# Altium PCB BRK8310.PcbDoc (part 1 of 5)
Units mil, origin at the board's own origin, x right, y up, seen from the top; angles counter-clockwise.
Board outline 6600.39 x 4492.13 mil, 4 copper layers (L1-Top, L2-GND, L3-GND, L4-BOT), stack 60.25 mil thick; 119 components, 266 nets, 1026 pads, 596 vias.
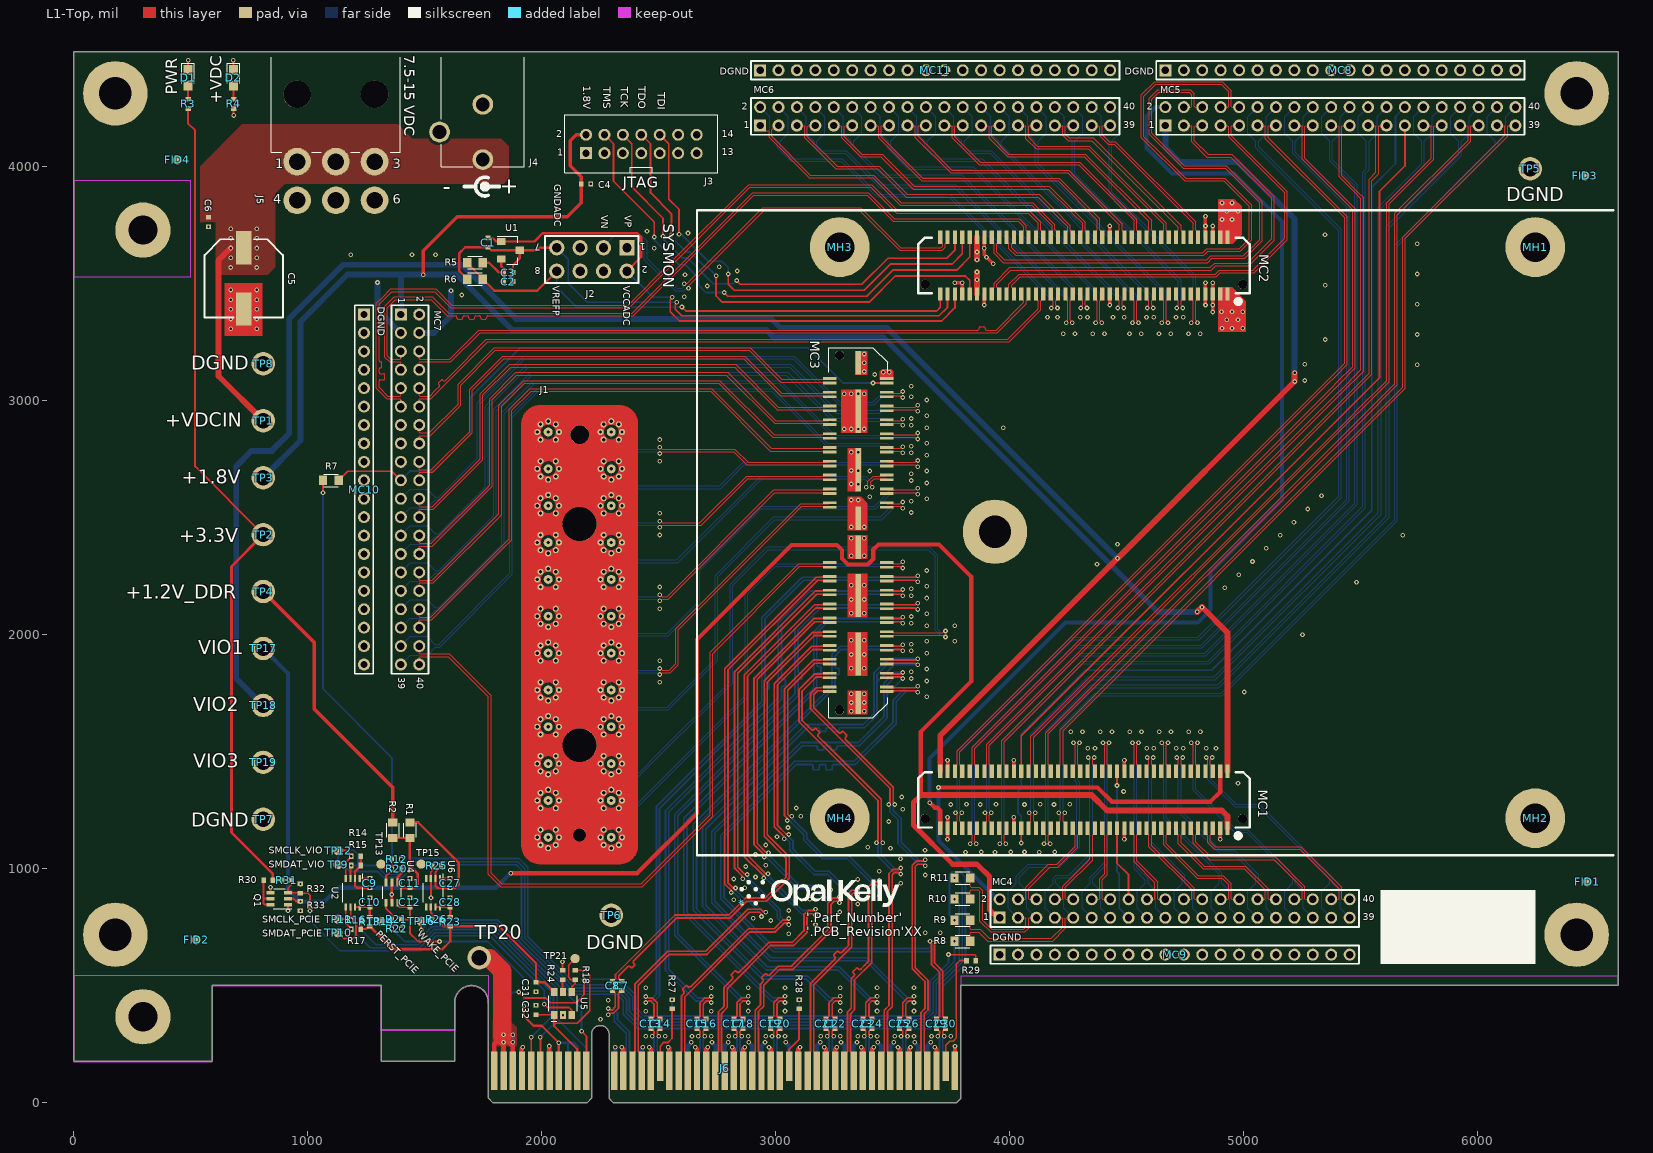
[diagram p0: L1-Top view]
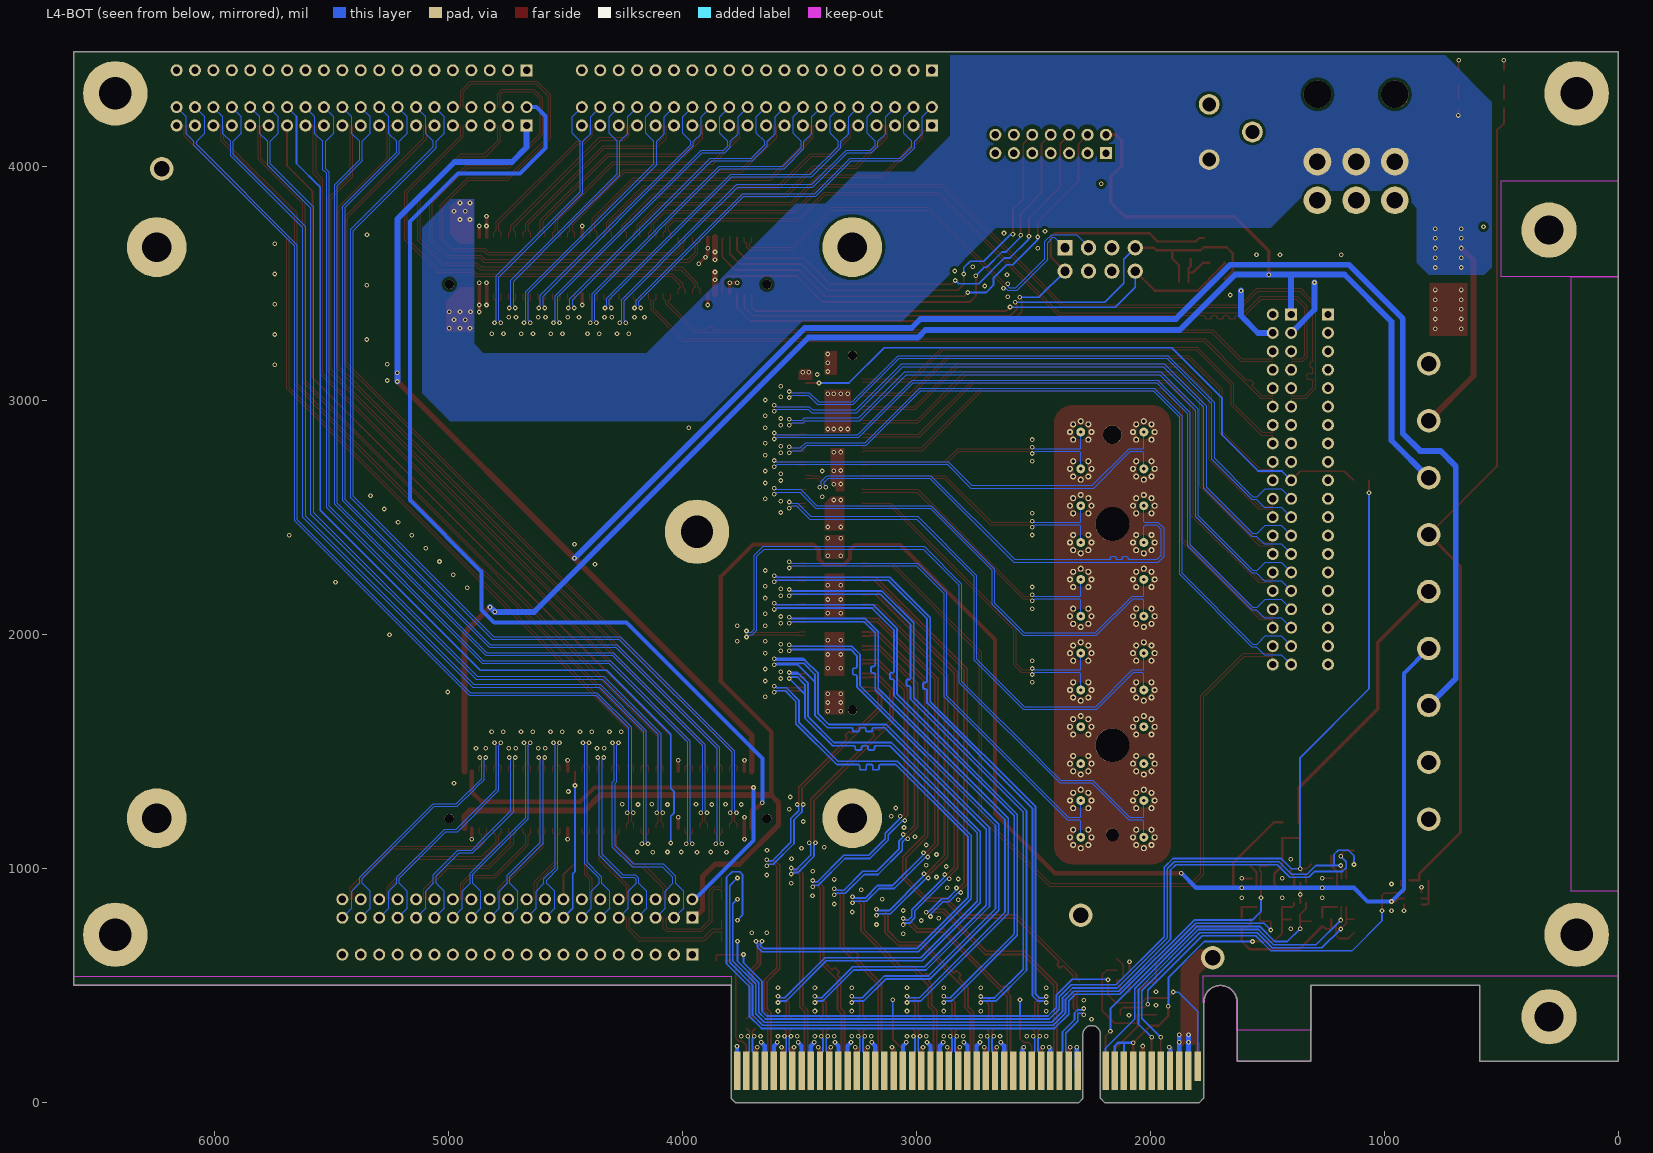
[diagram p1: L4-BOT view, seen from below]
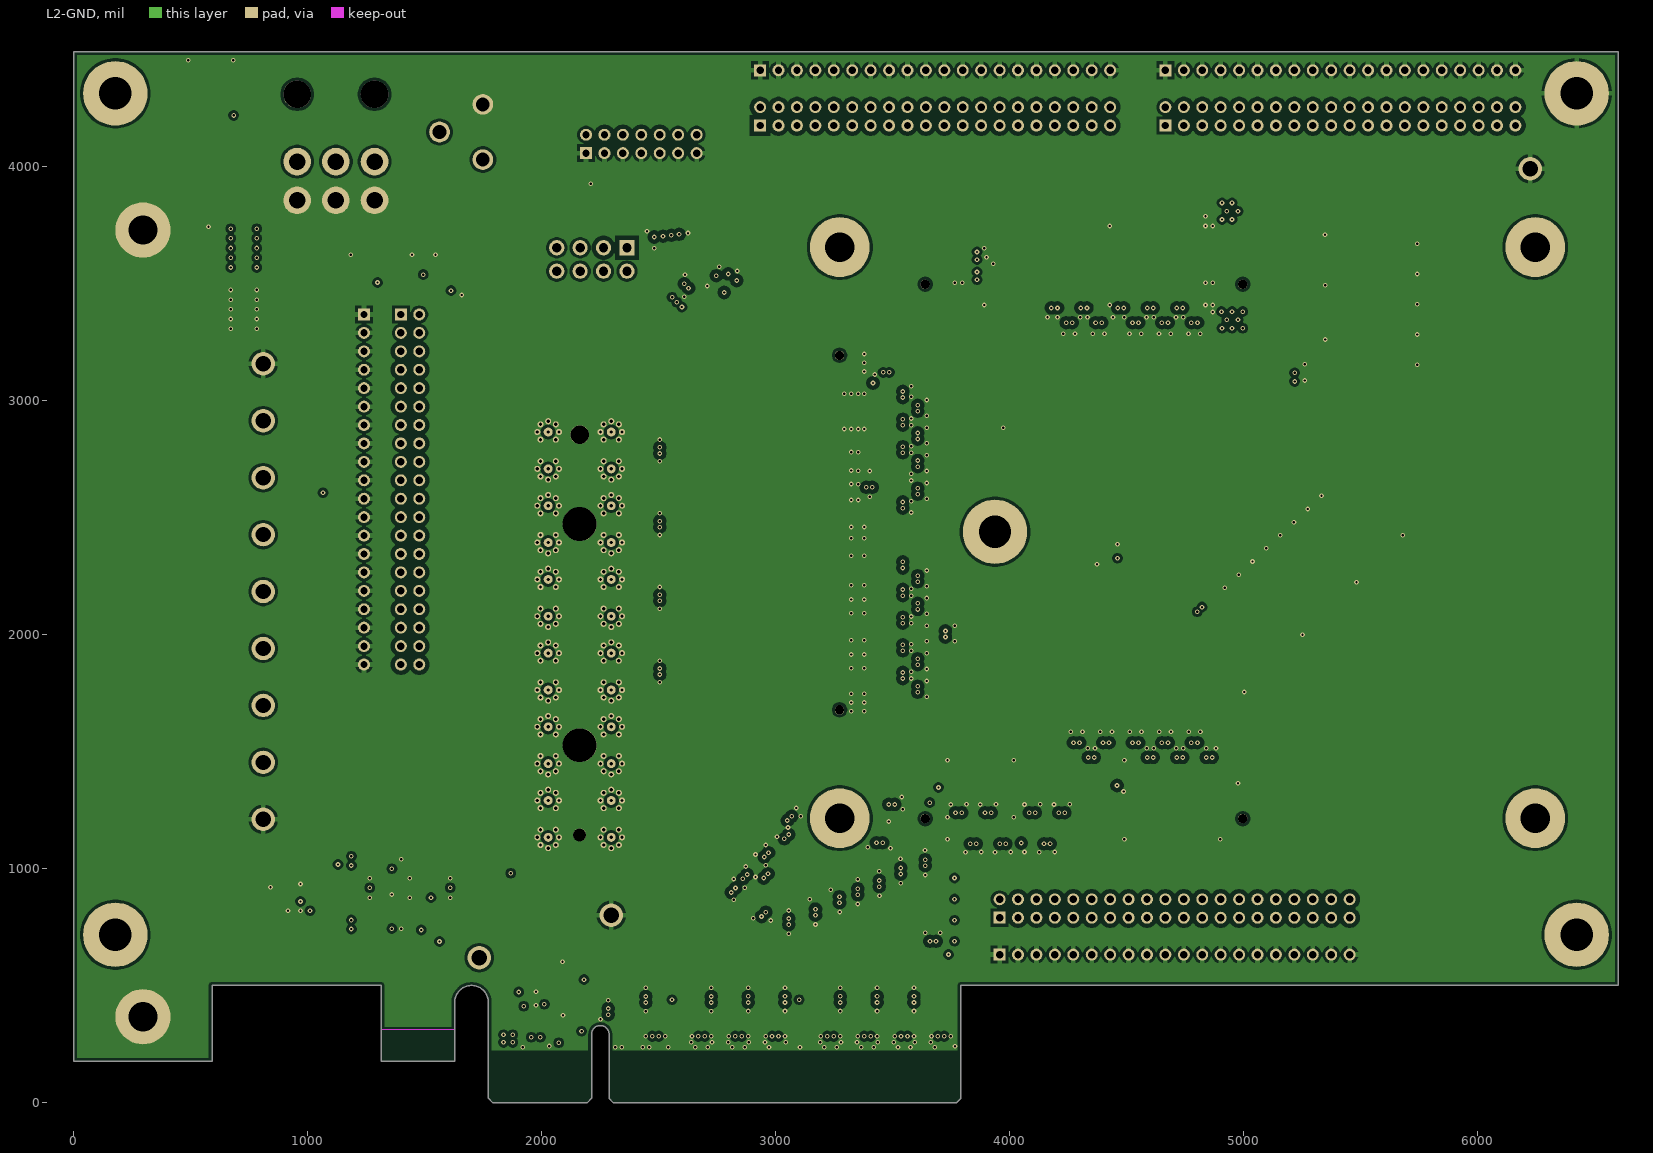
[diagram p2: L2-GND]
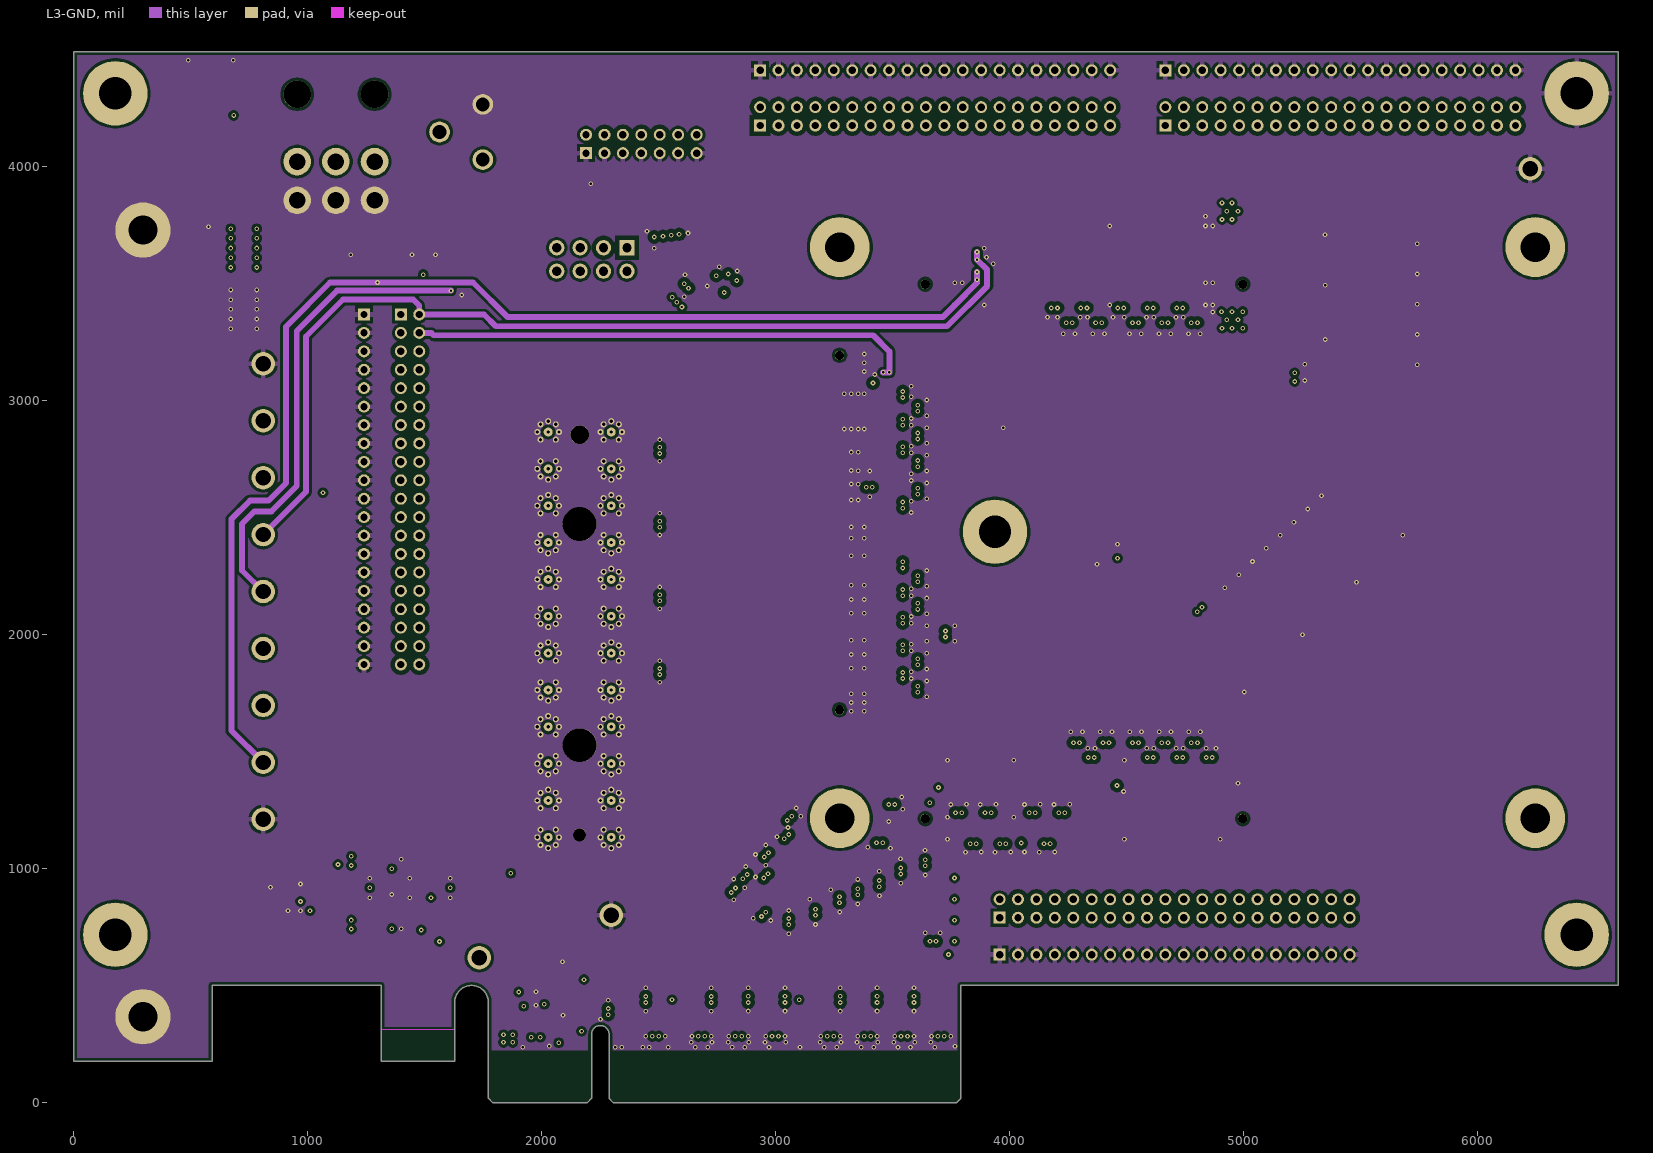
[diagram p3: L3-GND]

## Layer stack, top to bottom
Top Solder: solder mask 0.4, Solder Resist, Dk 3.5
L1-Top: signal copper 1.4
Dielectric 2: prepreg 5.08, IT180A, Dk 4.2
L2-GND: signal copper 1.4
Dielectric 1: core 44.49, IT180A, Dk 4.2
L3-GND: signal copper 1.4
Dielectric 3: prepreg 5.08, IT180A, Dk 4.2
L4-BOT: signal copper 1.4
Solder Side: solder mask 0.4, Solder Resist, Dk 3.5

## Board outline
590.54,177.16 590.54,501.97 1312.98,501.97 1312.98,177.16 1627.94,177.16 1627.94,430.12 cw(c1699.8,430.12) 1771.65,430.12 1771.65,19.68 1791.33,0 2192.91,0 2212.59,19.68 2212.59,293.31 cw(c2249.99,293.31) 2287.39,293.31 2287.39,19.68 2307.08,0 3771.65,0 3791.33,19.68 3791.33,501.97 6600.39,501.97 6600.39,4492.13 -0.01,4492.13 -0.01,177.16

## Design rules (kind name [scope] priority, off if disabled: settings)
BoardOutlineClearance [not HasFootprint('PCIEx8-FULL-HEIGHT')] p1: gap=15 ignorepadtopadclearanceinfootprint=FALSE
Clearance Clearance_50ohmSpace [InNetClass('50ohm') vs InNetClass('50ohm')] p1: gap=6 ignorepadtopadclearanceinfootprint=FALSE except(7.5: Track-Hole; 18: Arc-Track Arc-Fill Arc-Poly Track-Track Track-Fill Track-Poly SMDPad-Fill SMDPad-Poly THPad-Fill THPad-Poly Via-Fill Via-Poly Fill-Fill Fill-Poly Poly-Poly)
Clearance Clearance_50ohm [InNetClass('50ohm')] p2: gap=6 ignorepadtopadclearanceinfootprint=FALSE except(7.5: Track-Hole; 18: Arc-Fill Arc-Poly Track-Fill Track-Poly SMDPad-Fill SMDPad-Poly THPad-Fill THPad-Poly Via-Fill Via-Poly Fill-Fill Fill-Poly Poly-Poly)
Clearance Clearance_diffPairOverride [(InDifferentialPairClass('100ohm_Diff') or InDifferentialPairClass('85ohm_diff')) and (((TouchesRoom('MC1') or TouchesRoom('MC2') or TouchesRoom('M.2')) and OnTop) or ((TouchesRoom('MC4') or TouchesRoom('MC6') or TouchesRoom('MC7') or TouchesRoom('MC8')) and OnBottom))] p3: gap=6 ignorepadtopadclearanceinfootprint=FALSE except(7.5: Track-Hole; 12: Arc-Fill Arc-Poly Track-Fill Track-Poly SMDPad-Fill SMDPad-Poly THPad-Fill THPad-Poly Via-Fill Via-Poly Fill-Fill Fill-Poly Poly-Poly Poly-Region Region-Region)
Clearance Clearance_diffPairVia [(InDifferentialPairClass('100ohm_Diff') or InDifferentialPairClass('85ohm_diff')) and (IsVia or IsPad) and not HasFootprint('SAMTEC_BDRA-92SJP-02-12-0100')] p4: gap=6 ignorepadtopadclearanceinfootprint=FALSE except(18: Arc-Fill Arc-Poly Arc-Region Track-Fill Track-Poly Track-Region SMDPad-Fill SMDPad-Poly SMDPad-Region THPad-Fill THPad-Poly THPad-Region Via-Fill Via-Poly Via-Region Fill-Fill Fill-Poly Fill-Region Poly-Poly Poly-Region Region-Region)
Clearance Clearance_diffPair [(InDifferentialPairClass('100ohm_Diff') or InDifferentialPairClass('85ohm_diff')) and not HasFootprint('SAMTEC_BDRA-92SJP-02-12-0100')] p5: gap=18 ignorepadtopadclearanceinfootprint=FALSE
Clearance [All] p6: gap=6 ignorepadtopadclearanceinfootprint=FALSE except(7.5: Track-Hole; 12: Arc-Fill Arc-Poly Track-Fill Track-Poly SMDPad-Fill SMDPad-Poly THPad-Fill THPad-Poly Via-Fill Via-Poly Fill-Fill Fill-Poly Poly-Poly Poly-Region Region-Region)
DiffPairsRouting 100ohm_diff [InDifferentialPairClass('100ohm_Diff')] p1: maxlimit=6 minlimit=1 mostfreqgap=6 toplayer_mingap=6 toplayer_minwidth=5.25 toplayer_maxwidth=5.25 toplayer_prefwidth=5.25 midlayer1_maxgap=1 midlayer1_prefgap=1 midlayer1_minwidth=1 midlayer1_maxwidth=1 midlayer1_prefwidth=1 midlayer2_maxgap=1 midlayer2_prefgap=1 midlayer2_minwidth=1 midlayer2_maxwidth=1 midlayer2_prefwidth=1 bottomlayer_mingap=6 bottomlayer_minwidth=5.25 bottomlayer_maxwidth=5.25 bottomlayer_prefwidth=5.25 maxuncoupledlength=500
DiffPairsRouting 85ohm_diff [InDifferentialPairClass('85ohm_diff')] p2: maxlimit=6 minlimit=1 mostfreqgap=6 toplayer_mingap=6 toplayer_minwidth=7.5 toplayer_maxwidth=7.5 toplayer_prefwidth=7.5 midlayer1_maxgap=1 midlayer1_prefgap=1 midlayer1_minwidth=1 midlayer1_maxwidth=1 midlayer1_prefwidth=1 midlayer2_maxgap=1 midlayer2_prefgap=1 midlayer2_minwidth=1 midlayer2_maxwidth=1 midlayer2_prefwidth=1 bottomlayer_mingap=6 bottomlayer_minwidth=7.5 bottomlayer_maxwidth=7.5 bottomlayer_prefwidth=7.5 maxuncoupledlength=500
DiffPairsRouting DiffPairsRouting_NotSet [All] p3: maxlimit=10 minlimit=10 mostfreqgap=10 toplayer_minwidth=15 toplayer_maxwidth=15 toplayer_prefwidth=15 midlayer1_minwidth=15 midlayer1_maxwidth=15 midlayer1_prefwidth=15 midlayer2_minwidth=15 midlayer2_maxwidth=15 midlayer2_prefwidth=15 bottomlayer_minwidth=15 bottomlayer_maxwidth=15 bottomlayer_prefwidth=15 maxuncoupledlength=500
FabricationTestPointUsage TestPointUsage [All] p1: valid=0 allowmultiple=FALSE
FabricationTestpoint Testpoint [All] p1: side=3 testpointundercomponent=TRUE minsize=40 maxsize=100 preferedsize=60 minholesize=0 maxholesize=40 preferedholesize=32 testpointgrid=1 allowsidetop=TRUE allowsidebottom=TRUE usegrid=TRUE gridtolerance=0.01
HoleSize [All] p1: absolutevalues=TRUE maxlimit=250 minlimit=8 maxpercent=80.000 minpercent=20.000
MatchedLengths [InxSignalClass('All xSignals')] p1: tolerance=5 checknetsindiffpair=TRUE checkdiffpairvsdiffpair=FALSE checkxsignals=FALSE checkothers=FALSE
MinimumAnnularRing [All] p1: minimumring=5
MinimumSolderMaskSliver [All] p1: minsoldermaskwidth=2
PlaneConnect [All] p1: planeconnectstyle=Direct reliefexpansion=20 reliefentries=4 reliefconductorwidth=10 reliefairgap=10
PolygonConnect "Via Connect" [IsVia] p1: connectstyle=Direct reliefconductorwidth=10 reliefentries=4 polygonreliefangle="90 Angle" airgapwidth=10
PolygonConnect PolygonConnectDirect [HasFootprint('SAMTEC_BDRA-92SJP-02-12-0100') or HasFootprint('CUI-PJ102A') or HasFootprint('0455580003')] p2: connectstyle=Direct reliefconductorwidth=20 reliefentries=4 polygonreliefangle="90 Angle" airgapwidth=12
PolygonConnect PolygonConnectGND [InNet('DGND')] p3: connectstyle=Relief reliefconductorwidth=22 reliefentries=4 polygonreliefangle="90 Angle" airgapwidth=12
PolygonConnect [All] p4: thpad.connectstyle=Relief thpad.reliefconductorwidth=20 thpad.reliefentries=4 thpad.polygonreliefangle="90 Angle" thpad.airgapwidth=12 smdpad.connectstyle=Direct smdpad.reliefconductorwidth=20 smdpad.reliefentries=4 smdpad.polygonreliefangle="90 Angle" smdpad.airgapwidth=12 via.connectstyle=Direct via.reliefconductorwidth=20 via.reliefentries=4 via.polygonreliefangle="90 Angle" via.airgapwidth=12
ReturnPath ReturnPath_Diff [(InDifferentialPairClass('100ohm_Diff') or InDifferentialPairClass('85ohm_diff')) and (not ((TouchesRoom('MC1') or TouchesRoom('MC2') or TouchesRoom('M.2')) and OnTop) and (not (TouchesRoom('MC4') or TouchesRoom('MC6') or TouchesRoom('MC7') or TouchesRoom('MC8')) and OnBottom)) and not TouchesRoom('PCIE')] p1: impedanceprofileid={FC3A9359-EA79-4C24-837F-E158A8B04174} _gaplimit=0 _useantipads=TRUE
ReturnPath ReturnPath_SE [InNetClass('50ohm') and (not ((TouchesRoom('MC1') or TouchesRoom('MC2') or TouchesRoom('M.2') or TouchesRoom('JTAG') or TouchesRoom('PERST')) and OnTop) and not ((TouchesRoom('MC4') or TouchesRoom('MC6') or TouchesRoom('MC7') or TouchesRoom('MC8')) and OnBottom))] p2: impedanceprofileid={70E1A7AF-9659-420A-8032-69FB668B1DC2} _gaplimit=0 _useantipads=TRUE
RoomDefinition PCIE [False] p1: confinementstyle=ConfineIn formatcopy=TRUE lockcomponents=FALSE outline 1761.41,228.35 3791.33,228.35 3791.33,-1.94 1761.41,-1.94
RoomDefinition PERST [False] p2: confinementstyle=ConfineIn formatcopy=TRUE lockcomponents=FALSE outline 1200.78,2738.71 1279.52,2738.71 1279.52,2659.09 1200.78,2659.09
RoomDefinition JTAG [False] p3: confinementstyle=ConfineIn formatcopy=TRUE lockcomponents=FALSE outline 2148,4180.92 2714.24,4180.92 2714.24,4009.77 2148,4009.77
RoomDefinition MC6 [False] p4: confinementstyle=ConfineIn formatcopy=TRUE lockcomponents=FALSE outline 4616.13,4303.15 6210.62,4303.15 6210.62,4133.86 4616.13,4133.86
RoomDefinition MC8 [False] p5: confinementstyle=ConfineIn formatcopy=TRUE lockcomponents=FALSE outline 1350.39,1826.3 1350.39,3420.78 1519.68,3420.78 1519.68,1826.3
RoomDefinition MC4 [False] p6: confinementstyle=ConfineIn formatcopy=TRUE lockcomponents=FALSE outline 3909.44,917.32 5503.93,917.32 5503.93,748.03 3909.44,748.03
RoomDefinition MC7 [False] p7: confinementstyle=ConfineIn formatcopy=TRUE lockcomponents=FALSE outline 2883.85,4303.15 4478.34,4303.15 4478.34,4133.86 2883.85,4133.86
RoomDefinition MC2 [False] p8: confinementstyle=ConfineIn formatcopy=TRUE lockcomponents=FALSE outline 3590.54,3748.03 5047.24,3748.03 5047.24,3409.45 3590.54,3409.45
RoomDefinition MC1 [False] p9: confinementstyle=ConfineIn formatcopy=TRUE lockcomponents=FALSE outline 3586.61,1464.57 5047.24,1464.57 5047.24,1125.98 3586.61,1125.98
RoutingLayers [All] p1: top layer_v5=TRUE mid layer 1_v5=TRUE mid layer 2_v5=FALSE bottom layer_v5=TRUE
RoutingVias [All] p1: holewidth=10 width=20 viastyle="Through Hole" minholewidth=10 minwidth=20 maxholewidth=50 maxwidth=100
SilkToSilkClearance [All] p1: silktosilkclearance=0.1
SilkToSolderMaskClearance SilkscreenOverComponentPads [IsPad] p1: minsilkscreentomaskgap=2 clearancetoexposedcopper=TRUE
SolderMaskExpansion [All] p1: expansion=2 istentingtop=FALSE
ViasUnderSMD [All] p1: allowed=TRUE
Width Width_50ohm [InNetClass('50ohm')] p1: maxlimit=7.5 minlimit=7.5 preferedwidth=7.5 minimp=50.000000 maximp=50.000000 favimp=50.000000
Width okWidth [All] p2: maxlimit=150 minlimit=7 preferedwidth=8 minimp=50.000000 maximp=50.000000 favimp=50.000000
21 further rules are at their usual default settings.

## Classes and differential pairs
net class JTAG: JTAG_TCK JTAG_TDI JTAG_TDO JTAG_TMS
net class okPwr: +1.2V_DDR +1.8V +3.3V +3.3V_PCIE_C +3.3VAUX_PCIE +3.3VAUX_PCIE_C +12V_PCIE_C +VDCIN VIO1 VIO2 VIO3
net class 50ohm: B64_T0U_N12 B64_T1U_N12 B64_T2U_N12 B64_T3U_N12 B67_T3U_N12 JTAG_TCK JTAG_TDI JTAG_TDO JTAG_TMS
differential pair class 85ohm_diff: DP_MGT_REFCLK1_225_C DP_MGT_RX0_224 DP_MGT_RX0_225 DP_MGT_RX1_224 DP_MGT_RX1_225 DP_MGT_RX2_224 DP_MGT_RX2_225 DP_MGT_RX3_224 DP_MGT_RX3_225 DP_MGT_TX0_224 DP_MGT_TX0_225 DP_MGT_TX1_224 DP_MGT_TX1_225 DP_MGT_TX2_224 DP_MGT_TX2_225 DP_MGT_TX3_224 DP_MGT_TX3_225 DP_PCIE_REFCLK_C DP_PCIE_RX0 DP_PCIE_RX1 DP_PCIE_RX2 DP_PCIE_RX3 DP_PCIE_RX4 DP_PCIE_RX5 DP_PCIE_RX6 DP_PCIE_RX7
component class "PCIE X8": C7 C8 C9 C10 C11 C12 C13 C14 C15 C16 C17 C18 C19 C20 C21 C22 C23 C24 C25 C26 C27 C28 C29 C30 C31 C32 J6 Q1 R12 R13 R14 R15 R16 R17 R18 R20 R21 R22 R23 R24 R25 R26 R27 R28 R29 R30 R31 R32 R33 TP9 TP10 TP11 TP12 TP13 TP14 TP15 TP16 TP20 TP21 U2 U4 U5 U6
component class BRK8310: * ASSY1 C1 C2 C3 C4 C5 C6 D1 D2 FID1 FID2 FID3 FID4 J1 J2 J3 J4 J5 LABEL1 MC1 MC2 MC3 MC4 MC5 MC6 MC7 MC8 MC9 MC10 MC11 MH1 MH2 MH3 MH4 PCB1 R1 R2 R3 R4 R5 R6 R7 R8 R9 R10 R11 TP1 TP2 TP3 TP4 TP5 TP6 TP7 TP8 TP17 TP18 TP19 U1
differential pair class 100ohm_diff: DP_100MHZ_OSC_ DP_B64_L1 DP_B64_L2 DP_B64_L3 DP_B64_L4 DP_B64_L5 DP_B64_L6 DP_B64_L7 DP_B64_L8 DP_B64_L9 DP_B64_L10 DP_B64_L11_GC DP_B64_L12_GC DP_B64_L13_GC DP_B64_L14_GC DP_B64_L15 DP_B64_L16 DP_B64_L17 DP_B64_L18 DP_B64_L19 DP_B64_L20 DP_B64_L21 DP_B64_L22 DP_B64_L23 DP_B64_L24 DP_B67_L13_GC DP_B67_L14_GC DP_B67_L15 DP_B67_L16 DP_B67_L17 DP_B67_L18 DP_B67_L19 DP_B67_L20 DP_B67_L21 DP_B67_L22 DP_B67_L23 DP_B67_L24 DP_B84_L1 DP_B84_L2 DP_B84_L3 DP_B84_L4 DP_B84_L5_HDGC DP_B84_L6_HDGC DP_B84_L7_HDGC DP_B84_L8_HDGC DP_B84_L9 DP_B84_L10 DP_B84_L11 DP_B84_L12 DP_B86_L1 DP_B86_L2 DP_B86_L3 DP_B86_L4 DP_B86_L5_HDGC DP_B86_L6_HDGC DP_B86_L7_HDGC DP_B86_L8_HDGC DP_B86_L9 DP_B86_L10 DP_B86_L11 DP_B86_L12 DP_B87_L1 DP_B87_L2 DP_B87_L3 DP_B87_L4 DP_B87_L5_HDGC DP_B87_L6_HDGC DP_B87_L7_HDGC DP_B87_L8_HDGC DP_B87_L9 DP_B87_L10 DP_B87_L11 DP_B87_L12 DP_MGT_REFCLK0_224_C DP_MGT_REFCLK0_226_C DP_MGT_RX0_226 DP_MGT_RX1_226 DP_MGT_RX2_226 DP_MGT_RX3_226 DP_MGT_TX0_226 DP_MGT_TX1_226 DP_MGT_TX2_226 DP_MGT_TX3_226 DP_XADC_V DP_XADC_V_C
differential pair DP_XADC_V: +XADC_VP_C -XADC_VN_C
differential pair DP_PCIE_RX4: +PCIE_RX4P_C -PCIE_RX4N_C
differential pair DP_PCIE_RX5: +PCIE_RX5P_C -PCIE_RX5N_C
differential pair DP_PCIE_RX6: +PCIE_RX6P_C -PCIE_RX6N_C
differential pair DP_PCIE_RX7: +PCIE_RX7P_C -PCIE_RX7N_C
differential pair DP_PCIE_RX0: +PCIE_RX0P_C -PCIE_RX0N_C
differential pair DP_PCIE_RX1: +PCIE_RX1P_C -PCIE_RX1N_C
differential pair DP_PCIE_RX2: +PCIE_RX2P_C -PCIE_RX2N_C
differential pair DP_PCIE_RX3: +PCIE_RX3P_C -PCIE_RX3N_C
differential pair DP_PCIE_REFCLK_C: +PCIE_REFCLKP_C -PCIE_REFCLKN_C
differential pair DP_MGT_REFCLK0_226_C: +MGT_REFCLK0N_226_C -MGT_REFCLK0P_226_C
differential pair DP_MGT_REFCLK1_225_C: +MGT_REFCLK1N_225_C -MGT_REFCLK1P_225_C
differential pair DP_MGT_RX0_224: +MGT_RXN0_224 -MGT_RXP0_224
differential pair DP_MGT_RX0_225: +MGT_RXN0_225 -MGT_RXP0_225
differential pair DP_MGT_RX0_226: +MGT_RXN0_226 -MGT_RXP0_226
differential pair DP_MGT_RX1_224: +MGT_RXN1_224 -MGT_RXP1_224
differential pair DP_MGT_RX1_225: +MGT_RXN1_225 -MGT_RXP1_225
differential pair DP_MGT_RX1_226: +MGT_RXN1_226 -MGT_RXP1_226
differential pair DP_MGT_RX2_224: +MGT_RXN2_224 -MGT_RXP2_224
differential pair DP_MGT_RX2_225: +MGT_RXN2_225 -MGT_RXP2_225
differential pair DP_MGT_RX2_226: +MGT_RXN2_226 -MGT_RXP2_226
differential pair DP_MGT_RX3_224: +MGT_RXN3_224 -MGT_RXP3_224
differential pair DP_MGT_RX3_225: +MGT_RXN3_225 -MGT_RXP3_225
differential pair DP_MGT_RX3_226: +MGT_RXN3_226 -MGT_RXP3_226
differential pair DP_MGT_TX0_224: +MGT_TXN0_224 -MGT_TXP0_224
differential pair DP_MGT_TX0_225: +MGT_TXN0_225 -MGT_TXP0_225
differential pair DP_MGT_TX0_226: +MGT_TXN0_226 -MGT_TXP0_226
differential pair DP_MGT_TX1_224: +MGT_TXN1_224 -MGT_TXP1_224
differential pair DP_MGT_TX1_225: +MGT_TXN1_225 -MGT_TXP1_225
differential pair DP_MGT_TX1_226: +MGT_TXN1_226 -MGT_TXP1_226
differential pair DP_MGT_TX2_224: +MGT_TXN2_224 -MGT_TXP2_224
differential pair DP_MGT_TX2_225: +MGT_TXN2_225 -MGT_TXP2_225
differential pair DP_MGT_TX2_226: +MGT_TXN2_226 -MGT_TXP2_226
differential pair DP_MGT_TX3_224: +MGT_TXN3_224 -MGT_TXP3_224
differential pair DP_MGT_TX3_225: +MGT_TXN3_225 -MGT_TXP3_225
differential pair DP_MGT_TX3_226: +MGT_TXN3_226 -MGT_TXP3_226
differential pair DP_XADC_V_C: +XADC_VN_C -XADC_VP_C
differential pair DP_MGT_REFCLK0_224_C: +MGT_REFCLK0N_224_C -MGT_REFCLK0P_224_C
differential pair DP_100MHZ_OSC_: +"" -""
differential pair DP_B64_L1: +B64_L1N -B64_L1P
differential pair DP_B64_L2: +B64_L2N -B64_L2P
differential pair DP_B64_L3: +B64_L3N -B64_L3P
differential pair DP_B64_L4: +B64_L4N -B64_L4P
differential pair DP_B64_L5: +B64_L5N -B64_L5P
differential pair DP_B64_L6: +B64_L6N -B64_L6P
differential pair DP_B64_L7: +B64_L7N -B64_L7P
differential pair DP_B64_L8: +B64_L8N -B64_L8P
differential pair DP_B64_L9: +B64_L9N -B64_L9P
differential pair DP_B64_L10: +B64_L10N -B64_L10P
differential pair DP_B64_L11_GC: +B64_L11N_GC -B64_L11P_GC
differential pair DP_B64_L12_GC: +B64_L12N_GC -B64_L12P_GC
differential pair DP_B64_L13_GC: +B64_L13N_GC -B64_L13P_GC
differential pair DP_B64_L14_GC: +B64_L14N_GC -B64_L14P_GC
differential pair DP_B64_L15: +B64_L15N -B64_L15P
differential pair DP_B64_L16: +B64_L16N -B64_L16P
differential pair DP_B64_L17: +B64_L17N -B64_L17P
differential pair DP_B64_L18: +B64_L18N -B64_L18P
differential pair DP_B64_L19: +B64_L19N -B64_L19P
differential pair DP_B64_L20: +B64_L20N -B64_L20P
differential pair DP_B64_L21: +B64_L21N -B64_L21P
differential pair DP_B64_L22: +B64_L22N -B64_L22P
differential pair DP_B64_L23: +B64_L23N -B64_L23P
differential pair DP_B64_L24: +B64_L24N -B64_L24P
differential pair DP_B67_L13_GC: +B67_L13N_GC -B67_L13P_GC
differential pair DP_B67_L14_GC: +B67_L14N_GC -B67_L14P_GC
differential pair DP_B67_L15: +B67_L15N -B67_L15P
differential pair DP_B67_L16: +B67_L16N -B67_L16P
differential pair DP_B67_L17: +B67_L17N -B67_L17P
differential pair DP_B67_L18: +B67_L18N -B67_L18P
differential pair DP_B67_L19: +B67_L19N -B67_L19P
differential pair DP_B67_L20: +B67_L20N -B67_L20P
differential pair DP_B67_L21: +B67_L21N -B67_L21P
differential pair DP_B67_L22: +B67_L22N -B67_L22P
differential pair DP_B67_L23: +B67_L23N -B67_L23P
differential pair DP_B67_L24: +B67_L24N -B67_L24P
differential pair DP_B84_L1: +B84_L1N -B84_L1P
differential pair DP_B84_L2: +B84_L2N -B84_L2P
differential pair DP_B84_L3: +B84_L3N -B84_L3P
differential pair DP_B84_L4: +B84_L4N -B84_L4P
differential pair DP_B84_L5_HDGC: +B84_L5N_HDGC -B84_L5P_HDGC
differential pair DP_B84_L6_HDGC: +B84_L6N_HDGC -B84_L6P_HDGC
differential pair DP_B84_L7_HDGC: +B84_L7N_HDGC -B84_L7P_HDGC
differential pair DP_B84_L8_HDGC: +B84_L8N_HDGC -B84_L8P_HDGC
differential pair DP_B84_L9: +B84_L9N -B84_L9P
differential pair DP_B84_L10: +B84_L10N -B84_L10P
differential pair DP_B84_L11: +B84_L11N -B84_L11P
differential pair DP_B84_L12: +B84_L12N -B84_L12P
differential pair DP_B86_L1: +B86_L1N -B86_L1P
differential pair DP_B86_L2: +B86_L2N -B86_L2P
differential pair DP_B86_L3: +B86_L3N -B86_L3P
differential pair DP_B86_L4: +B86_L4N -B86_L4P
differential pair DP_B86_L5_HDGC: +B86_L5N_HDGC -B86_L5P_HDGC
differential pair DP_B86_L6_HDGC: +B86_L6N_HDGC -B86_L6P_HDGC
differential pair DP_B86_L7_HDGC: +B86_L7N_HDGC -B86_L7P_HDGC
differential pair DP_B86_L8_HDGC: +B86_L8N_HDGC -B86_L8P_HDGC
differential pair DP_B86_L9: +B86_L9N -B86_L9P
differential pair DP_B86_L10: +B86_L10N -B86_L10P
differential pair DP_B86_L11: +B86_L11N -B86_L11P
differential pair DP_B86_L12: +B86_L12N -B86_L12P
differential pair DP_B87_L1: +B87_L1N -B87_L1P
differential pair DP_B87_L2: +B87_L2N -B87_L2P
differential pair DP_B87_L3: +B87_L3N -B87_L3P
differential pair DP_B87_L4: +B87_L4N -B87_L4P
differential pair DP_B87_L5_HDGC: +B87_L5N_HDGC -B87_L5P_HDGC
differential pair DP_B87_L6_HDGC: +B87_L6N_HDGC -B87_L6P_HDGC
differential pair DP_B87_L7_HDGC: +B87_L7N_HDGC -B87_L7P_HDGC
differential pair DP_B87_L8_HDGC: +B87_L8N_HDGC -B87_L8P_HDGC
differential pair DP_B87_L9: +B87_L9N -B87_L9P
differential pair DP_B87_L10: +B87_L10N -B87_L10P
differential pair DP_B87_L11: +B87_L11N -B87_L11P
differential pair DP_B87_L12: +B87_L12N -B87_L12P

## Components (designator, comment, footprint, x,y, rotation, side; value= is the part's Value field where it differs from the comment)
* "Opal Kelly Logo" okLogo-23x5-2021 2854.34,853.25 r0 top
C1 "C0402C104K8PACTU" CAPC1005X06A#1 1770.65,3676.69 r270 top value="0.1 u"
C2 "GRM155C80J106ME11D" CAPC1005X06A#1 1856.53,3509.73 r180 top value=10u
C3 "C0402C104K8PACTU" CAPC1005X06A#1 1856.53,3548.96 r0 top value="0.1 u"
C4 "C0402C104K8PACTU" CAPC1005X06A#1 2189.12,3927.72 r0 top value="0.1 u"
C5 "EEE-FK1E221P" CAPAE9083X70N 726.17,3523.62 r270 top value=220u
C6 "TMK105BJ104KV-F" CAPC1005X06A#2 575.78,3764.76 r90 top value="0.1 u"
C7 "C0402C104K8PACTU" CAPC1005X06A#2 2341.62,500.15 r90 top value="0.1 u"
C8 "C0402C104K8PACTU" CAPC1005X06A#2 2302.25,500.15 r90 top value="0.1 u"
C9 "C0402C104K8PACTU" CAPC1005X06A#2 1264.9,939.74 r270 top value="0.1 u"
C10 "C0402C104K8PACTU" CAPC1005X06A#2 1264.9,857.07 r270 top value="0.1 u"
C11 "C0402C104K8PACTU" CAPC1005X06A#2 1436.16,939.35 r270 top value="0.1 u"
C12 "C0402C104K8PACTU" CAPC1005X06A#2 1436.16,856.67 r270 top value="0.1 u"
C13 "C0402C104K8PACTU" CAPC1005X06A#1 2466.53,338.58 r90 top value="0.1 u"
C14 "C0402C104K8PACTU" CAPC1005X06A#1 2505.9,338.58 r90 top value="0.1 u"
C15 "C0402C104K8PACTU" CAPC1005X06A#1 2663.38,338.58 r90 top value="0.1 u"
C16 "C0402C104K8PACTU" CAPC1005X06A#1 2702.75,338.58 r90 top value="0.1 u"
C17 "C0402C104K8PACTU" CAPC1005X06A#1 2820.86,338.58 r90 top value="0.1 u"
C18 "C0402C104K8PACTU" CAPC1005X06A#1 2860.23,338.58 r90 top value="0.1 u"
C19 "C0402C104K8PACTU" CAPC1005X06A#1 2978.34,338.58 r90 top value="0.1 u"
C20 "C0402C104K8PACTU" CAPC1005X06A#1 3017.71,338.58 r90 top value="0.1 u"
C21 "C0402C104K8PACTU" CAPC1005X06A#2 3214.56,338.58 r90 top value="0.1 u"
C22 "C0402C104K8PACTU" CAPC1005X06A#2 3253.93,338.58 r90 top value="0.1 u"
C23 "C0402C104K8PACTU" CAPC1005X06A#2 3372.04,338.58 r90 top value="0.1 u"
C24 "C0402C104K8PACTU" CAPC1005X06A#2 3411.41,338.58 r90 top value="0.1 u"
C25 "C0402C104K8PACTU" CAPC1005X06A#2 3529.52,338.58 r90 top value="0.1 u"
C26 "C0402C104K8PACTU" CAPC1005X06A#2 3568.89,338.58 r90 top value="0.1 u"
C27 "C0402C104K8PACTU" CAPC1005X06A#2 1608.41,939.35 r270 top value="0.1 u"
C28 "C0402C104K8PACTU" CAPC1005X06A#2 1608.41,856.67 r270 top value="0.1 u"
C29 "C0402C104K8PACTU" CAPC1005X06A#2 3687,338.58 r90 top value="0.1 u"
C30 "C0402C104K8PACTU" CAPC1005X06A#2 3726.37,338.58 r90 top value="0.1 u"
C31 "C0402C104K8PACTU" CAPC1005X06A#1 1975.47,495.16 r90 top value="0.1 u"
C32 "C0402C104K8PACTU" CAPC1005X06A#1 1975.47,397 r270 top value="0.1 u"
D1 "+3.3VDD" CD1608-0603-PIN1-CATHODE 488.36,4381.84 r270 top
D2 "+VDC" CD1608-0603-PIN1-CATHODE 681.88,4381.84 r270 top
FID1 "FIDUCIAL" FID1MM/2MM-SS 6468.5,944.88 r90 top
FID2 "FIDUCIAL" FID1MM/2MM-SS 523.62,696.85 r90 top
FID3 "FIDUCIAL" FID1MM/2MM-SS 6458.27,3962.19 r90 top
FID4 "FIDUCIAL" FID1MM/2MM-SS 442.52,4030.04 r90 top
J1 "BDRA-92SJP-02-12-0100" SAMTEC_BDRA-92SJP-02-12-0100 2162.11,2000.88 r90 top locked
J2 "PRPC004DAAN-RC" HDR2X4 2363.92,3654.69 r180 top locked
J3 "87831-1420" XILINX-JTAG 2425.34,4098.42 r0 top locked
J4 "PJ-102AH" CUI-PJ102A 1748.02,4570.87 r180 top locked
J5 "0455580003" 0455580003 1119.91,4023.04 r0 top locked
J6 "PCIe x8 Card-Edge Connector" PCIEx8-FULL-HEIGHT 2249.99,0 r0 top locked
MC1 "BTE-040-01-F-D-A" BTE-040 4316.92,1295.27 r180 top locked
MC2 "BTE-040-01-F-D-A" BTE-040 4316.92,3578.74 r180 top locked
MC3 "QTH-040-01-F-D-DP-A" QTH-040-01-X-D-DP-A 3352.35,2437.01 r90 top locked
MC4 "0877584016" HDR2X20-2MM 4704.72,830.71 r0 top locked
MC5 "0877584016" HDR2X20-2MM 5413.38,4216.53 r0 top locked
MC6 "0877584016" HDR2X20-2MM 3681.09,4216.53 r0 top locked
MC7 "0877584016" HDR2X20-2MM 1437,2621.57 r270 top locked
MC8 "Header, 20-Pin, Single Row" HDR1X20-2MM 5413.38,4413.38 r0 top locked
MC9 "Header, 20-Pin, Single Row" HDR1X20-2MM 4704.72,633.86 r0 top locked
MC10 "Header, 20-Pin, Single Row" HDR1X20-2MM 1240.15,2621.57 r270 top locked
MC11 "Header, 20-Pin, Single Row" HDR1X20-2MM 3681.09,4413.38 r0 top locked
MH1 "MTG" MTG-3.2/6.5-PTH 6246.06,3657.48 r180 top locked
MH2 "MTG" MTG-3.2/6.5-PTH 6246.06,1216.53 r180 top locked
MH3 "MTG" MTG-3.2/6.5-PTH 3273.61,3657.48 r0 top
MH4 "MTG" MTG-3.2/6.5-PTH 3273.61,1216.53 r0 top locked
Q1 "SI1922EDH-T1-GE3" SOT363-6N 878,872.82 r180 top
R1 "CRCW06030000Z0EA" RESC1608N 1436.16,1165.31 r90 top value=0
R2 "CRCW06030000Z0EA" RESC1608N 1363.39,1165.31 r90 top value=0
R3 "CRCW0402549RFKED" RESC1005X06A 488.36,4269.69 r270 top value=549
R4 "CRCW04022K00FKED" RESC1005X06A 682.87,4269.69 r270 top value="2.0 k"
R5 "CRCW06030000Z0EA" RESC1608N 1714.27,3591.06 r180 top value=0
R6 "CRCW06030000Z0EA" RESC1608N 1714.27,3520.41 r0 top value=0
R7 "CRCW06030000Z0EA" RESC1608N 1098.43,2660.94 r0 top value=0
R8 "CRCW06030000Z0EA" RESC1608N 3797.52,690.4 r0 top value=0
R9 "CRCW06030000Z0EA" RESC1608N 3797.52,780.66 r0 top value=0
R10 "CRCW06030000Z0EA" RESC1608N 3797.72,870.92 r0 top value=0
R11 "CRCW06030000Z0EA" RESC1608N 3797.72,961.18 r0 top value=0
R12 "NoLoad" RESC1005X06A 1379.08,1040.98 r180 top
R13 "CRCW0402200KFKED" RESC1005X06A 1264.9,774.39 r270 top value="200 k"
R14 "CRCW04024K75FKED" RESC1005X06A 1205.85,1053.92 r0 top value="4.75 k"
R15 "CRCW04024K75FKED" RESC1005X06A 1205.85,1014.55 r0 top value="4.75 k"
R16 "NoLoad" RESC1005X06A 1205.85,782.26 r0 top
R17 "NoLoad" RESC1005X06A 1205.85,742.89 r0 top
R18 "CRCW0402100KFKED" RESC1005X06A 2142.43,546.46 r90 top value="100 k"
R20 "NoLoad" RESC1005X06A 1379.08,1000.77 r0 top
R21 "NoLoad" RESC1005X06A 1379.08,784.23 r0 top
R22 "NoLoad" RESC1005X06A 1379.08,744.86 r180 top
R23 "CRCW0402200KFKED" RESC1005X06A 1608.41,774.39 r270 top value="200 k"
R24 "CRCW0402100KFKED" RESC1005X06A 2088.57,546.46 r270 top value="100 k"
R25 "CRCW0402100KFKED" RESC1005X06A 1551.32,1012.58 r0 top value="100 k"
R26 "NoLoad" RESC1005X06A 1551.32,784.23 r0 top
R27 "CRCW04020000Z0ED" RESC1005X06A 2556.62,421.26 r90 top value=0
R28 "CRCW04020000Z0ED" RESC1005X06A 3099.84,421.26 r90 top value=0
R29 "CRCW04020000Z0ED" RESC1005X06A 3834.84,608.27 r0 top value=0
R30 "CRCW04024K75FKED" RESC1005X06A 830.75,951.56 r0 top value="4.75 k"
R31 "CRCW04024K75FKED" RESC1005X06A 909.49,951.56 r180 top value="4.75 k"
R32 "CRCW0402100KFKED" RESC1005X06A 968.55,916.12 r270 top value="100 k"
R33 "CRCW0402100KFKED" RESC1005X06A 968.55,841.32 r90 top value="100 k"
TP1 "+VDCIN" TP-PTH-65/100 809.29,2915.59 r270 top
TP2 "+3.3V" TP-PTH-65/100 809.29,2428.82 r0 top
TP3 "+1.8V" TP-PTH-65/100 809.29,2672.2 r90 top
TP4 "+1.2V_DDR" TP-PTH-65/100 809.29,2185.43 r180 top
TP5 "DGND" TP-PTH-65/100 6224.41,3992.13 r90 top
TP6 "DGND" TP-PTH-65/100 2296.96,801.95 r90 top
TP7 "DGND" TP-PTH-65/100 809.29,1211.89 r90 top
TP8 "DGND" TP-PTH-65/100 809.29,3158.97 r90 top
TP9 "SMDAT_VIO" TP-SMD40 1129.01,1018.75 r90 top
TP10 "SMDAT_PCIE" TP-SMD40 1129.01,727.15 r90 top
TP11 "SMCLK_PCIE" TP-SMD40 1129.01,785.03 r180 top
TP12 "SMCLK_VIO" TP-SMD40 1129.01,1078.33 r180 top
TP13 "PERST_VIO" TP-SMD40 1312.15,1020.45 r180 top
TP14 "PERST_PCIE" TP-SMD40 1312.15,776.36 r180 top
TP15 "WAKE_VIO" TP-SMD40 1484.39,1020.45 r180 top
TP16 "WAKE_PCIE" TP-SMD40 1484.39,776.36 r180 top
TP17 "VIO1" TP-PTH-65/100 809.29,1942.04 r0 top
TP18 "VIO2" TP-PTH-65/100 809.29,1698.66 r0 top
TP19 "VIO3" TP-PTH-65/100 809.29,1455.27 r0 top
TP20 "+12V_PCIE_C" TP-PTH-65/100 1732.73,620.68 r270 top
TP21 "FAULT" TP-SMD40 2142.43,616.85 r270 top
U1 "REF3012AIDBZT" SOT23-95P240X110 1866.53,3644.21 r270 top
U2 "PCA9306DCUR" PCA9306DCU 1192.07,898.41 r270 top
U4 "SN74AXC1T45DCK" DCK-R-PDSO-G6 1359.39,898.41 r180 top
U5 "AP22653AW6-7" AP2265XW6 2090.54,424.41 r90 top
U6 "PCA9306DCUR" PCA9306DCU 1535.57,898.41 r270 top

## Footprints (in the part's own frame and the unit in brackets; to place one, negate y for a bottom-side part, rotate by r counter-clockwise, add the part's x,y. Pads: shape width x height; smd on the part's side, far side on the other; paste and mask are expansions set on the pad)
0455580003 [mm]
  round 3 hole 3 unplated: 0(-4.2,7.3) 0(4.2,7.3)
  round 3 hole 1.8: 1(-4.2,0) 2(0,0) 3(4.2,0) 4(-4.2,-4.2) 5(0,-4.2) 6(4.2,-4.2)
  silkscreen extent -7,1 7,11.31
AP2265XW6 [mm]
  rect 0.9x0.7 smd: 1(-1.25,0.95) 2(-1.25,0) 3(-1.25,-0.95) 4(1.25,-0.95) 5(1.25,0) 6(1.25,0.95)
  silkscreen extent -1.9,-1.55 0.85,1.55
BTE-040 [mm] "0.8mm Samtech socket"
  rect 0.46x1.45 smd: 1(-15.6,3.085) 2(-15.6,-3.085) 3(-14.8,3.085) 4(-14.8,-3.085) 5(-14,3.085) 6(-14,-3.085) 7(-13.2,3.085) 8(-13.2,-3.085) 9(-12.4,3.085) 10(-12.4,-3.085) 11(-11.6,3.085) 12(-11.6,-3.085) 13(-10.8,3.085) 14(-10.8,-3.085) 15(-10,3.085) 16(-10,-3.085) 17(-9.2,3.085) 18(-9.2,-3.085) 19(-8.4,3.085) 20(-8.4,-3.085) 21(-7.6,3.085) 22(-7.6,-3.085) 23(-6.8,3.085) 24(-6.8,-3.085) 25(-6,3.085) 26(-6,-3.085) 27(-5.2,3.085) 28(-5.2,-3.085) 29(-4.4,3.085) 30(-4.4,-3.085) 31(-3.6,3.085) 32(-3.6,-3.085) 33(-2.8,3.085) 34(-2.8,-3.085) 35(-2,3.085) 36(-2,-3.085) 37(-1.2,3.085) 38(-1.2,-3.085) 39(-0.4,3.085) 40(-0.4,-3.085) 41(0.4,3.085) 42(0.4,-3.085) 43(1.2,3.085) 44(1.2,-3.085) 45(2,3.085) 46(2,-3.085) 47(2.8,3.085) 48(2.8,-3.085) 49(3.6,3.085) 50(3.6,-3.085) 51(4.4,3.085) 52(4.4,-3.085) 53(5.2,3.085) 54(5.2,-3.085) 55(6,3.085) 56(6,-3.085) 57(6.8,3.085) 58(6.8,-3.085) 59(7.6,3.085) 60(7.6,-3.085) 61(8.4,3.085) 62(8.4,-3.085) 63(9.2,3.085) 64(9.2,-3.085) 65(10,3.085) 66(10,-3.085) 67(10.8,3.085) 68(10.8,-3.085) 69(11.6,3.085) 70(11.6,-3.085) 71(12.4,3.085) 72(12.4,-3.085) 73(13.2,3.085) 74(13.2,-3.085) 75(14,3.085) 76(14,-3.085) 77(14.8,3.085) 78(14.8,-3.085) 79(15.6,3.085) 80(15.6,-3.085)
  round 1.02 hole 1.02 unplated: 81(-17.235,2.035) 82(17.235,2.035)
  silkscreen extent -18,-3 18,4.15
CAPAE9083X70N [mm] "Aluminum Electrolytic Capacitor, Body 8.30x8.30x7.00mm, IPC Medium Density"
  rect 3.6x1.65 smd: 1(-3.325,0) 2(3.325,0)
  silkscreen extent -4.25,-4.25 4.25,4.25
CAPC1005X06A#1 [mm] "Chip Capacitor, 2-Leads, Body 1.00x0.50mm, OK custom footprint"
  rect 0.52x0.55 smd: 1(-0.51,0) 2(0.51,0)
CAPC1005X06A#2 [mm] "Chip Capacitor, 2-Leads, Body 1.00x0.50mm, OK custom footprint"
  rect 0.52x0.55 smd mask+0.051: 1(-0.51,0) 2(0.51,0)
CD1608-0603-PIN1-CATHODE [mm] "Chip Diode; Body 1.6 x 0.8 mm (LxW typ)"
  rect 1.1x1 smd: 1(-0.85,0) 2(0.85,0)
  silkscreen extent -1.58,-0.68 0.6,0.68
CUI-PJ102A [mm] "2.1mm/5.5mm DC power jack"
  round 2.25 hole 1.5: 1(0,13.7) 2(0,7.7) 3(4.7,10.7)
  silkscreen extent -4.5,2.6 4.5,14.5
DCK-R-PDSO-G6 [mm]
  rect 0.35x0.85 smd: 1(-0.65,-1.1) 2(0,-1.1) 3(0.65,-1.1) 4(0.65,1.1) 5(0,1.1) 6(-0.65,1.1)
  silkscreen extent -1.01,-1.55 1.01,0.65
FID1MM/2MM-SS [mm] "Fiducial 1mm copper, 2mm soldermask, single-side"
  round 1 smd paste-0.5 mask+0.5: FID?(0,0)
HDR1X20-2MM [mm] "2mm 1x20 Header"
  rect 1.3x1.3 hole 0.8: 1(-19,0)
  round 1.3 hole 0.8: 2(-17,0) 3(-15,0) 4(-13,0) 5(-11,0) 6(-9,0) 7(-7,0) 8(-5,0) 9(-3,0) 10(-1,0) 11(1,0) 12(3,0) 13(5,0) 14(7,0) 15(9,0) 16(11,0) 17(13,0) 18(15,0) 19(17,0) 20(19,0)
  silkscreen extent -20,-1 20,1
HDR2X4 [mil] "0.1\" 2x4 header"
  rect 65x65 hole 40: 1(0,0)
  round 65 hole 40: 2(0,100) 3(100,0) 4(100,100) 5(200,0) 6(200,100) 7(300,0) 8(300,100)
  silkscreen extent -50,-50 350,150
HDR2X20-2MM [mm] "2mm 2x20 header"
  rect 1.3x1.3 hole 0.8: 1(-19,-1)
  round 1.3 hole 0.8: 2(-19,1) 3(-17,-1) 4(-17,1) 5(-15,-1) 6(-15,1) 7(-13,-1) 8(-13,1) 9(-11,-1) 10(-11,1) 11(-9,-1) 12(-9,1) 13(-7,-1) 14(-7,1) 15(-5,-1) 16(-5,1) 17(-3,-1) 18(-3,1) 19(-1,-1) 20(-1,1) 21(1,-1) 22(1,1) 23(3,-1) 24(3,1) 25(5,-1) 26(5,1) 27(7,-1) 28(7,1) 29(9,-1) 30(9,1) 31(11,-1) 32(11,1) 33(13,-1) 34(13,1) 35(15,-1) 36(15,1) 37(17,-1) 38(17,1) 39(19,-1) 40(19,1)
  silkscreen extent -20,-2 20,2
MTG-3.2/6.5-PTH [mm] "Mounting hole, 3.2mm ID, 6.5mm OD, plated"
  round 6.5 hole 3.2: 1(0,0)
okLogo-23x5-2021 [mil] "Opal Kelly silkscreen logo (23mm x 5mm) - 2021 update"
  silkscreen extent -4,-15 672,100
PCA9306DCU [mm]
  rect 0.75x0.25 smd: 1(-1.55,0.75) 2(-1.55,0.25) 3(-1.55,-0.25) 4(-1.55,-0.75) 5(1.55,-0.75) 6(1.55,-0.25) 7(1.55,0.25) 8(1.55,0.75)
  silkscreen extent -2.03,-1.09 1.02,1.09
PCIEx8-FULL-HEIGHT [mm] "PCI Express 8-lane edge connector, full height"
  rect 0.7x3.2 smd far side paste-2.54: A1(-11.5,4)
  rect 0.7x4.2 smd far side paste-2.54: A2(-10.5,3.5) A3(-9.5,3.5) A4(-8.5,3.5) A5(-7.5,3.5) A6(-6.5,3.5) A7(-5.5,3.5) A8(-4.5,3.5) A9(-3.5,3.5) A10(-2.5,3.5) A11(-1.5,3.5) A12(1.5,3.5) A13(2.5,3.5) A14(3.5,3.5) A15(4.5,3.5) A16(5.5,3.5) A17(6.5,3.5) A18(7.5,3.5) A19(8.5,3.5) A20(9.5,3.5) A21(10.5,3.5) A22(11.5,3.5) A23(12.5,3.5) A24(13.5,3.5) A25(14.5,3.5) A26(15.5,3.5) A27(16.5,3.5) A28(17.5,3.5) A29(18.5,3.5) A30(19.5,3.5) A31(20.5,3.5) A32(21.5,3.5) A33(22.5,3.5) A34(23.5,3.5) A35(24.5,3.5) A36(25.5,3.5) A37(26.5,3.5) A38(27.5,3.5) A39(28.5,3.5) A40(29.5,3.5) A41(30.5,3.5) A42(31.5,3.5) A43(32.5,3.5) A44(33.5,3.5) A45(34.5,3.5) A46(35.5,3.5) A47(36.5,3.5) A48(37.5,3.5) A49(38.5,3.5)
  rect 0.7x4.2 smd paste-2.54: B1(-11.5,3.5) B2(-10.5,3.5) B3(-9.5,3.5) B4(-8.5,3.5) B5(-7.5,3.5) B6(-6.5,3.5) B7(-5.5,3.5) B8(-4.5,3.5) B9(-3.5,3.5) B10(-2.5,3.5) B11(-1.5,3.5) B12(1.5,3.5) B13(2.5,3.5) B14(3.5,3.5) B15(4.5,3.5) B16(5.5,3.5) B18(7.5,3.5) B19(8.5,3.5) B20(9.5,3.5) B21(10.5,3.5) B22(11.5,3.5) B23(12.5,3.5) B24(13.5,3.5) B25(14.5,3.5) B26(15.5,3.5) B27(16.5,3.5) B28(17.5,3.5) B29(18.5,3.5) B30(19.5,3.5) B32(21.5,3.5) B33(22.5,3.5) B34(23.5,3.5) B35(24.5,3.5) B36(25.5,3.5) B37(26.5,3.5) B38(27.5,3.5) B39(28.5,3.5) B40(29.5,3.5) B41(30.5,3.5) B42(31.5,3.5) B43(32.5,3.5) B44(33.5,3.5) B45(34.5,3.5) B46(35.5,3.5) B47(36.5,3.5) B49(38.5,3.5)
  rect 0.7x3.2 smd paste-2.54: B17(6.5,4) B31(20.5,4) B48(37.5,4)
  L1-Top keep-out region: 39.15,12.75 110.5,12.75 110.5,13.75 39.15,13.75
  L1-Top keep-out region: -57.15,4.45 -42.15,4.45 -42.131,4.453 -42.114,4.464 -42.103,4.481 -42.1,4.5 -42.1,4.5 -42.1,12.7 -23.85,12.7 -23.85,7.95 -23.847,7.931 -23.836,7.914 -23.819,7.903 -23.8,7.9 -23.8,7.9 -15.8,7.9 -15.781,7.903 -15.764,7.914 -15.753,7.931 -15.75,7.95 -15.75,7.95 -15.75,7.95 -15.75,7.951 -15.75,7.951 -15.75,10.925 -15.574,11.695 -15.081,12.312 -14.37,12.655 -13.58,12.655 -12.869,12.312 -12.376,11.695 -12.2,10.925 -12.2,10.925 -12.195,10.903 -12.181,10.886 -12.161,10.876 -12.139,10.876 -12.119,10.886 -12.105,10.903 -12.1,10.925 -12.1,10.925 -12.1,13.75 -12.103,13.769 -12.114,13.786 -12.131,13.797 -12.15,13.8 -12.15,13.8 -57.15,13.8
  L4-BOT keep-out region: 39.15,12.75 110.5,12.75 110.5,13.75 39.15,13.75
  L4-BOT keep-out region: -57.15,4.45 -42.15,4.45 -42.131,4.453 -42.114,4.464 -42.103,4.481 -42.1,4.5 -42.1,4.5 -42.1,12.7 -23.85,12.7 -23.85,7.95 -23.847,7.931 -23.836,7.914 -23.819,7.903 -23.8,7.9 -23.8,7.9 -15.8,7.9 -15.781,7.903 -15.764,7.914 -15.753,7.931 -15.75,7.95 -15.75,7.95 -15.75,7.95 -15.75,7.951 -15.75,7.951 -15.75,10.925 -15.574,11.695 -15.081,12.312 -14.37,12.655 -13.58,12.655 -12.869,12.312 -12.376,11.695 -12.2,10.925 -12.2,10.925 -12.195,10.903 -12.181,10.886 -12.161,10.876 -12.139,10.876 -12.119,10.886 -12.105,10.903 -12.1,10.925 -12.1,10.925 -12.1,13.75 -12.103,13.769 -12.114,13.786 -12.131,13.797 -12.15,13.8 -12.15,13.8 -57.15,13.8
  Keep-Out Layer region: -23.8,4.5 -15.8,4.5 -15.8,7.95 -23.8,7.95
QTH-040-01-X-D-DP-A [mm] "0.5mm hi-speed, high-density header (female), 80-pin, non-latching, ground protection in middle"
  rect 2.54x0.64 smd: 0(-18.44,0) 0(-1.56,0) 0(1.56,0) 0(18.44,0)
  rect 4.7x0.64 smd: 0(-13.17,0) 0(-6.82,0) 0(6.83,0) 0(13.18,0)
  rect 0.3x1.45 smd: 1(-17.25,3.09) 2(-17.25,-3.09) 3(-16.75,3.09) 4(-16.75,-3.09) 5(-15.75,3.09) 6(-15.75,-3.09) 7(-15.25,3.09) 8(-15.25,-3.09) 9(-14.25,3.09) 10(-14.25,-3.09) 11(-13.75,3.09) 12(-13.75,-3.09) 13(-12.75,3.09) 14(-12.75,-3.09) 15(-12.25,3.09) 16(-12.25,-3.09) 17(-11.25,3.09) 18(-11.25,-3.09) 19(-10.75,3.09) 20(-10.75,-3.09) 21(-9.75,3.09) 22(-9.75,-3.09) 23(-9.25,3.09) 24(-9.25,-3.09) 25(-8.25,3.09) 26(-8.25,-3.09) 27(-7.75,3.09) 28(-7.75,-3.09) 29(-6.75,3.09) 30(-6.75,-3.09) 31(-6.25,3.09) 32(-6.25,-3.09) 33(-5.25,3.09) 34(-5.25,-3.09) 35(-4.75,3.09) 36(-4.75,-3.09) 37(-3.75,3.09) 38(-3.75,-3.09) 39(-3.25,3.09) 40(-3.25,-3.09) 41(2.75,3.09) 42(2.75,-3.09) 43(3.25,3.09) 44(3.25,-3.09) 45(4.25,3.09) 46(4.25,-3.09) 47(4.75,3.09) 48(4.75,-3.09) 49(5.75,3.09) 50(5.75,-3.09) 51(6.25,3.09) 52(6.25,-3.09) 53(7.25,3.09) 54(7.25,-3.09) 55(7.75,3.09) 56(7.75,-3.09) 57(8.75,3.09) 58(8.75,-3.09) 59(9.25,3.09) 60(9.25,-3.09) 61(10.25,3.09) 62(10.25,-3.09) 63(10.75,3.09) 64(10.75,-3.09) 65(11.75,3.09) 66(11.75,-3.09) 67(12.25,3.09) 68(12.25,-3.09) 69(13.25,3.09) 70(13.25,-3.09) 71(13.75,3.09) 72(13.75,-3.09) 73(14.75,3.09) 74(14.75,-3.09) 75(15.25,3.09) 76(15.25,-3.09) 77(16.25,3.09) 78(16.25,-3.09) 79(16.75,3.09) 80(16.75,-3.09)
  round 1.02 hole 1.02 unplated paste+0: MH(-19.24,2.03) MH(19.24,2.03)
  silkscreen extent -20.1,-3.2 20.1,3.2
RESC1005X06A [mm] "Chip Resistor, 2-Leads, Body 1.00x0.50mm, OK custom footprint"
  rect 0.5x0.6 smd mask+0.051: 1(-0.5,0) 2(0.5,0)
RESC1608N [mm] "Chip Resistor, Body 1.6x0.8mm, IPC Medium Density"
  rect 0.9x1 smd: 1(-0.85,0) 2(0.85,0)
  silkscreen extent -0.77,-0.68 0.78,0.68, body extent -0.85,-0.48 0.85,0.48, height 0.6
SAMTEC_BDRA-92SJP-02-12-0100 [mm]
  round 0.97 hole 0.36: A01(-21.995,3.425) A02(-17.995,3.425) A03(-13.995,3.425) A04(-9.995,3.425) A05(-5.995,3.425) A06(-1.995,3.425) A07(2.005,3.425) A08(6.005,3.425) A09(10.005,3.425) A10(14.005,3.425) A11(18.005,3.425) A12(22.005,3.425) B01(-21.995,-3.425) B02(-17.995,-3.425) B03(-13.995,-3.425) B04(-9.995,-3.425) B05(-5.995,-3.425) B06(-1.995,-3.425) B07(2.005,-3.425) B08(6.005,-3.425) B09(10.005,-3.425) B10(14.005,-3.425) B11(18.005,-3.425) B12(22.005,-3.425)
  round 0.66 hole 0.36 mask+0: GND1(-23.165,-3.425) GND1(-23.165,3.425) GND1(-22.822,-4.252) GND1(-22.822,-2.598) GND1(-22.822,2.598) GND1(-22.822,4.252) GND1(-21.995,-4.595) GND1(-21.995,-2.255) GND1(-21.995,2.255) GND1(-21.995,4.595) GND1(-21.168,-4.252) GND1(-21.168,-2.598) GND1(-21.168,2.598) GND1(-21.168,4.252) GND1(-18.822,-4.252) GND1(-18.822,-2.598) GND1(-18.822,2.598) GND1(-18.822,4.252) GND1(-17.995,-4.595) GND1(-17.995,-2.255) GND1(-17.995,2.255) GND1(-17.995,4.595) GND1(-17.168,-4.252) GND1(-17.168,-2.598) GND1(-17.168,2.598) GND1(-17.168,4.252) GND1(-16.825,-3.425) GND1(-16.825,3.425) GND1(-15.165,-3.425) GND1(-15.165,3.425) GND1(-14.822,-4.252) GND1(-14.822,-2.598) GND1(-14.822,2.598) GND1(-14.822,4.252) GND1(-13.995,-4.595) GND1(-13.995,-2.255) GND1(-13.995,2.255) GND1(-13.995,4.595) GND1(-13.168,-4.252) GND1(-13.168,-2.598) GND1(-13.168,2.598) GND1(-13.168,4.252) GND1(-10.822,-4.252) GND1(-10.822,-2.598) GND1(-10.822,2.598) GND1(-10.822,4.252) GND1(-9.995,-4.595) GND1(-9.995,-2.255) GND1(-9.995,2.255) GND1(-9.995,4.595) GND1(-9.168,-4.252) GND1(-9.168,-2.598) GND1(-9.168,2.598) GND1(-9.168,4.252) GND1(-8.825,-3.425) GND1(-8.825,3.425) GND1(-7.165,-3.425) GND1(-7.165,3.425) GND1(-6.822,-4.252) GND1(-6.822,-2.598) GND1(-6.822,2.598) GND1(-6.822,4.252) GND1(-5.995,-4.595) GND1(-5.995,-2.255) GND1(-5.995,2.255) GND1(-5.995,4.595) GND1(-5.168,-4.252) GND1(-5.168,-2.598) GND1(-5.168,2.598) GND1(-5.168,4.252) GND1(-2.822,4.252) GND1(-2.822,-2.598) GND1(-2.822,2.598) GND1(-2.822,-4.252) GND1(-1.995,4.595) GND1(-1.995,-2.255) GND1(-1.995,2.255) GND1(-1.995,-4.595) GND1(-1.168,2.598) GND1(-1.168,4.252) GND1(-1.168,-4.252) GND1(-1.168,-2.598) GND1(-0.825,3.425) GND1(-0.825,-3.425) GND1(0.835,3.425) GND1(0.835,-3.425) GND1(1.178,2.598) GND1(1.178,4.252) GND1(1.178,-4.252) GND1(1.178,-2.598) GND1(2.005,4.595) GND1(2.005,-2.255) GND1(2.005,2.255) GND1(2.005,-4.595) GND1(2.832,4.252) GND1(2.832,-2.598) GND1(2.832,2.598) GND1(2.832,-4.252) GND1(5.178,-4.252) GND1(5.178,-2.598) GND1(5.178,2.598) GND1(5.178,4.252) GND1(6.005,-4.595) GND1(6.005,-2.255) GND1(6.005,2.255) GND1(6.005,4.595) GND1(6.832,-4.252) GND1(6.832,-2.598) GND1(6.832,2.598) GND1(6.832,4.252) GND1(7.175,-3.425) GND1(7.175,3.425) GND1(8.835,-3.425) GND1(8.835,3.425) GND1(9.178,-4.252) GND1(9.178,-2.598) GND1(9.178,2.598) GND1(9.178,4.252) GND1(10.005,-4.595) GND1(10.005,-2.255) GND1(10.005,2.255) GND1(10.005,4.595) GND1(10.832,-4.252) GND1(10.832,-2.598) GND1(10.832,2.598) GND1(10.832,4.252) GND1(13.178,-4.252) GND1(13.178,-2.598) GND1(13.178,2.598) GND1(13.178,4.252) GND1(14.005,-4.595) GND1(14.005,-2.255) GND1(14.005,2.255) GND1(14.005,4.595) GND1(14.832,-4.252) GND1(14.832,-2.598) GND1(14.832,2.598) GND1(14.832,4.252) GND1(15.175,-3.425) GND1(15.175,3.425) GND1(16.835,-3.425) GND1(16.835,3.425) GND1(17.178,-4.252) GND1(17.178,-2.598) GND1(17.178,2.598) GND1(17.178,4.252) GND1(18.005,-4.595) GND1(18.005,-2.255) GND1(18.005,2.255) GND1(18.005,4.595) GND1(18.832,-4.252) GND1(18.832,-2.598) GND1(18.832,2.598) GND1(18.832,4.252) GND1(21.178,-4.252) GND1(21.178,-2.598) GND1(21.178,2.598) GND1(21.178,4.252) GND1(22.005,-4.595) GND1(22.005,-2.255) GND1(22.005,2.255) GND1(22.005,4.595) GND1(22.832,-4.252) GND1(22.832,-2.598) GND1(22.832,2.598) GND1(22.832,4.252) GND1(23.175,-3.425) GND1(23.175,3.425)
  round 1.4 hole 1.4 unplated: GND1(-21.72,0.005)
  round 3.68 hole 3.68 unplated mask+0: GND1(-11.995,0.005) GND1(12.005,0.005)
  round 2.03 hole 2.03 unplated: GND1(21.72,0.005)
  L1-Top region: 187 vertices and 0 holes, not listed, extent -24.895,-6.325 -21.995,6.325
  L1-Top region: 187 vertices and 0 holes, not listed, extent 22.005,-6.325 24.905,6.325
  L1-Top region: 249 vertices and 0 holes, not listed, extent -21.995,-6.325 -17.995,6.325
  L1-Top region: 249 vertices and 0 holes, not listed, extent -17.995,-6.325 -13.995,6.325
  L1-Top region: 249 vertices and 0 holes, not listed, extent -13.995,-6.325 -9.995,6.325
  L1-Top region: 249 vertices and 0 holes, not listed, extent -9.995,-6.325 -5.995,6.325
  L1-Top region: 249 vertices and 0 holes, not listed, extent -5.995,-6.325 -1.995,6.325
  L1-Top region: 249 vertices and 0 holes, not listed, extent -1.995,-6.325 2.005,6.325
  L1-Top region: 249 vertices and 0 holes, not listed, extent 2.005,-6.325 6.005,6.325
  L1-Top region: 249 vertices and 0 holes, not listed, extent 6.005,-6.325 10.005,6.325
  L1-Top region: 249 vertices and 0 holes, not listed, extent 10.005,-6.325 14.005,6.325
  L1-Top region: 249 vertices and 0 holes, not listed, extent 14.005,-6.325 18.005,6.325
  L1-Top region: 249 vertices and 0 holes, not listed, extent 18.005,-6.325 22.005,6.325
SOT23-95P240X110 [mm] "SOT-23; 3 Leads; Body 3.0 x 2.6 mm, inc. leads (LxW max)"
  rect 0.8x0.9 smd: 1(-0.95,-1) 2(0.95,-1) 3(0,1)
  silkscreen extent -1.53,-1.45 1.54,0.77
SOT363-6N [mm] "SOT363, 6-Leads, Body 2x1.3mm, Pitch 0.65mm, Lead Span 2.1mm, IPC Medium Density"
  rect 0.85x0.4 smd: 1(-0.95,0.65) 2(-0.95,0) 3(-0.95,-0.65) 4(0.95,-0.65) 5(0.95,0) 6(0.95,0.65)
  silkscreen extent -1.37,-1.09 0.63,1.09, body extent -0.63,-1 0.63,1, height 1
TP-PTH-65/100 [mil] "Test point, plated through-hole, 65/100mil"
  round 100 hole 65: 1(0,0)
TP-SMD40 [mm] "Test point, surface-mount, 40mil"
  round 1 smd paste-2: 1(0,0)
XILINX-JTAG [mm] "2mm 2x7 header"
  rect 1.3x1.3 hole 0.8: 1(-6,-1)
  round 1.3 hole 0.8: 2(-6,1) 3(-4,-1) 4(-4,1) 5(-2,-1) 6(-2,1) 7(0,-1) 8(0,1) 9(2,-1) 10(2,1) 11(4,-1) 12(4,1) 13(6,-1) 14(6,1)
  silkscreen extent -8.32,-3.15 8.32,3.15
